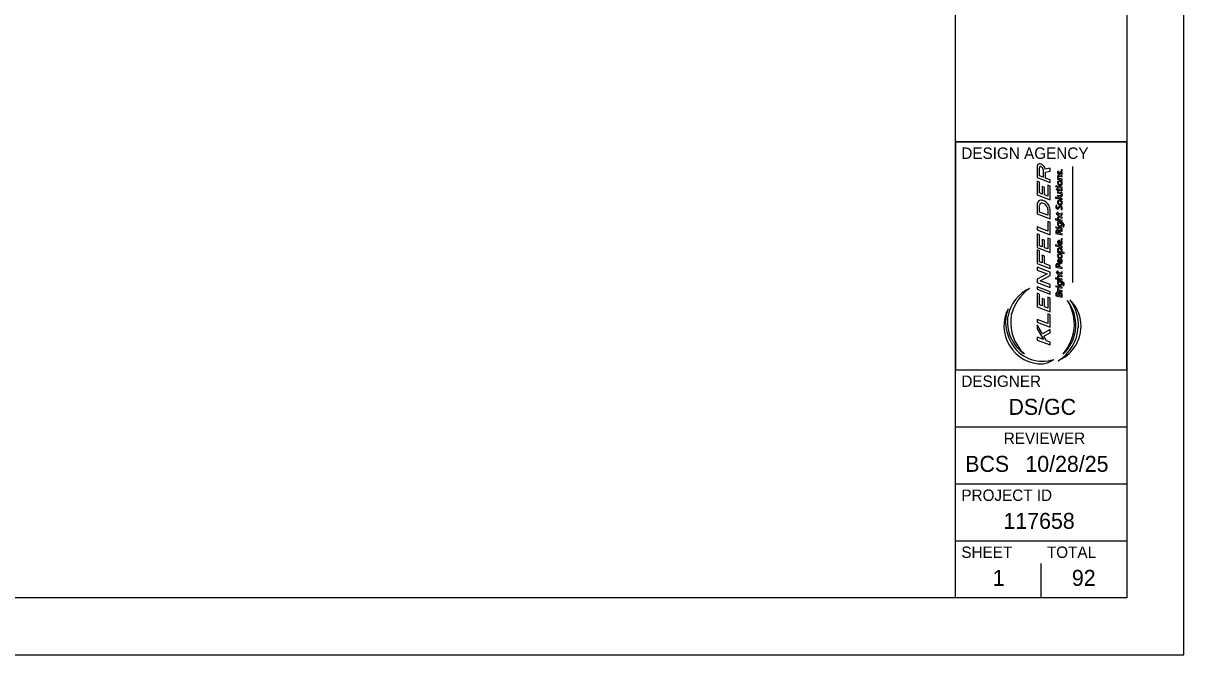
# Model space of a CAD drawing. Extents: x -107 to 120, y -81 to 213.
# Drawn here: x 27.71 to 37.89, y 1.57 to 7.11 of the extents above; entities that cross this region are included whole.
import ezdxf

# ---------------------------------------------------------------- set-up
doc = ezdxf.new("R2010")
doc.units = 0
for name, color, linetype in [('SC_Scratch1', 7, 'Continuous'), ('SH_Border', 7, 'Continuous'), ('SH_Cut_Line', 7, 'Continuous'), ('SH_Data', 7, 'Continuous'), ('SH_Text', 7, 'Continuous')]:
    doc.layers.add(name, color=color, linetype=linetype)

msp = doc.modelspace()

# ---------------------------------------------------------------- linework, layer by layer
at = {"layer": 'SC_Scratch1'}
msp.add_lwpolyline([(35.889, 4.068), (37.389, 4.068), (37.389, 6.068), (35.889, 6.068)], close=True, dxfattribs=at)
at = {"layer": 'SH_Border'}
for p, q in [((35.889, 2.068), (35.889, 23.068)), ((35.889, 6.068), (37.389, 6.068)), ((35.889, 4.068), (37.389, 4.068)), ((35.889, 3.568), (37.389, 3.568)), ((35.889, 3.068), (37.389, 3.068)), ((35.889, 2.568), (37.389, 2.568))]:
    msp.add_line(p, q, dxfattribs=at)
msp.add_lwpolyline([(5.389, 23.068), (37.389, 23.068), (37.389, 2.068), (5.389, 2.068)], close=True, dxfattribs=at)
at = {"layer": 'SH_Cut_Line'}
msp.add_lwpolyline([(3.889, 1.568), (37.889, 1.568), (37.889, 23.568), (3.889, 23.568)], close=True, dxfattribs=at)
at = {"layer": 'SH_Data'}
for p, q in [((36.639, 5.068), (36.639, 5.068)), ((36.639, 2.068), (36.639, 2.368)), ((36.264, 2.243), (36.264, 2.243))]:
    msp.add_line(p, q, dxfattribs=at)
at = {"layer": 'SH_Text'}
for p, q in [((36.624, 5.769), (36.624, 5.84)), ((36.79, 5.807), (36.784, 5.809)), ((36.816, 5.78), (36.822, 5.778)), ((36.814, 5.645), (36.789, 5.65)), ((36.823, 5.654), (36.817, 5.655)), ((36.777, 5.508), (36.769, 5.51)), ((36.813, 5.473), (36.821, 5.471)), ((36.823, 5.442), (36.817, 5.443)), ((36.825, 5.357), (36.782, 5.366)), ((36.831, 5.323), (36.838, 5.321)), ((36.791, 5.278), (36.791, 5.267)), ((36.799, 5.195), (36.799, 5.174)), ((36.822, 5.195), (36.815, 5.197)), ((36.799, 5.031), (36.799, 5.01)), ((36.822, 5.032), (36.815, 5.033)), ((36.794, 4.979), (36.794, 4.971)), ((36.801, 4.97), (36.801, 4.98)), ((36.823, 4.926), (36.817, 4.927)), ((36.825, 4.841), (36.782, 4.85)), ((36.831, 4.807), (36.838, 4.805)), ((36.792, 4.73), (36.792, 4.721)), ((36.817, 4.725), (36.817, 4.715))]:
    msp.add_line(p, q, dxfattribs=at)
for points in [[(36.604, 5.855), (36.604, 5.755), (36.718, 5.711), (36.718, 5.733), (36.676, 5.749), (36.676, 5.801), (36.718, 5.811), (36.718, 5.837), (36.675, 5.827)], [(36.655, 5.825), (36.655, 5.757), (36.624, 5.769)], [(36.815, 5.823), (36.815, 5.815), (36.823, 5.813), (36.823, 5.821), (36.815, 5.823)], [(36.913, 5.851), (36.913, 4.835)], [(36.604, 5.723), (36.604, 5.604), (36.718, 5.56), (36.718, 5.679), (36.698, 5.687), (36.698, 5.592), (36.669, 5.602), (36.669, 5.667), (36.648, 5.675), (36.648, 5.61), (36.624, 5.619), (36.624, 5.715), (36.604, 5.723)], [(36.788, 5.747), (36.782, 5.748), (36.782, 5.741), (36.823, 5.732), (36.823, 5.74), (36.8, 5.745)], [(36.795, 5.767), (36.823, 5.761), (36.823, 5.769), (36.798, 5.775)], [(36.766, 5.683), (36.766, 5.674), (36.774, 5.673), (36.774, 5.681), (36.766, 5.683)], [(36.789, 5.65), (36.789, 5.661), (36.782, 5.663), (36.782, 5.651), (36.77, 5.654), (36.773, 5.646), (36.782, 5.644), (36.782, 5.635), (36.789, 5.633), (36.789, 5.643), (36.813, 5.638)], [(36.782, 5.679), (36.782, 5.671), (36.823, 5.662), (36.823, 5.67), (36.782, 5.679)], [(36.817, 5.612), (36.823, 5.611), (36.823, 5.619), (36.782, 5.627), (36.782, 5.619), (36.806, 5.614)], [(36.81, 5.593), (36.782, 5.598), (36.782, 5.59), (36.807, 5.585)], [(36.604, 5.516), (36.604, 5.435), (36.718, 5.392), (36.718, 5.465)], [(36.697, 5.474), (36.697, 5.423), (36.625, 5.45), (36.625, 5.51)], [(36.764, 5.581), (36.764, 5.573), (36.823, 5.561), (36.823, 5.569), (36.764, 5.581)], [(36.782, 5.45), (36.782, 5.439), (36.77, 5.442), (36.773, 5.433), (36.782, 5.432), (36.782, 5.423), (36.789, 5.421), (36.789, 5.43), (36.813, 5.425)], [(36.814, 5.432), (36.789, 5.438), (36.789, 5.449), (36.782, 5.45)], [(36.797, 5.405), (36.823, 5.399), (36.823, 5.407), (36.797, 5.412)], [(36.604, 5.321), (36.604, 5.296), (36.718, 5.253), (36.718, 5.362), (36.698, 5.37), (36.698, 5.285), (36.604, 5.321)], [(36.787, 5.386), (36.763, 5.391), (36.763, 5.383), (36.823, 5.37), (36.823, 5.378), (36.802, 5.383)], [(36.766, 5.321), (36.766, 5.313), (36.774, 5.311), (36.774, 5.319), (36.766, 5.321)], [(36.782, 5.366), (36.782, 5.358), (36.789, 5.357)], [(36.782, 5.317), (36.782, 5.309), (36.823, 5.3), (36.823, 5.309), (36.782, 5.317)], [(36.803, 5.279), (36.823, 5.284), (36.823, 5.292), (36.8, 5.286)], [(36.648, 5.212), (36.648, 5.147), (36.624, 5.156), (36.624, 5.252), (36.604, 5.26), (36.604, 5.141), (36.718, 5.097), (36.718, 5.216), (36.698, 5.224), (36.698, 5.128), (36.669, 5.139), (36.669, 5.204), (36.648, 5.212)], [(36.768, 5.284), (36.768, 5.264), (36.823, 5.252), (36.823, 5.261), (36.798, 5.266), (36.798, 5.273)], [(36.791, 5.267), (36.774, 5.271), (36.774, 5.28)], [(36.809, 5.173), (36.805, 5.173), (36.805, 5.202), (36.802, 5.202)], [(36.815, 5.218), (36.815, 5.21), (36.823, 5.208), (36.823, 5.216), (36.815, 5.218)], [(36.648, 5.073), (36.648, 5.007), (36.625, 5.016), (36.625, 5.112), (36.604, 5.12), (36.604, 5.001), (36.718, 4.958), (36.718, 4.981), (36.669, 5), (36.669, 5.065), (36.648, 5.073)], [(36.764, 5.163), (36.764, 5.155), (36.823, 5.142), (36.823, 5.15), (36.764, 5.163)], [(36.788, 5.106), (36.782, 5.107), (36.782, 5.101), (36.84, 5.088), (36.84, 5.097), (36.818, 5.101)], [(36.768, 4.986), (36.768, 4.969), (36.823, 4.957), (36.823, 4.965), (36.801, 4.97)], [(36.809, 5.009), (36.805, 5.009), (36.805, 5.038), (36.802, 5.039)], [(36.604, 4.863), (36.604, 4.835), (36.718, 4.791), (36.718, 4.815), (36.63, 4.849), (36.718, 4.895), (36.718, 4.923), (36.604, 4.967), (36.604, 4.943), (36.691, 4.91), (36.604, 4.863)], [(36.782, 4.934), (36.782, 4.923), (36.77, 4.926), (36.773, 4.918), (36.782, 4.916), (36.782, 4.907), (36.789, 4.905), (36.789, 4.914), (36.813, 4.909)], [(36.794, 4.971), (36.774, 4.975), (36.774, 4.982)], [(36.814, 4.916), (36.789, 4.922), (36.789, 4.933), (36.782, 4.934)], [(36.797, 4.889), (36.823, 4.883), (36.823, 4.891), (36.797, 4.897)], [(36.604, 4.797), (36.604, 4.774), (36.718, 4.73), (36.718, 4.753), (36.604, 4.797)], [(36.787, 4.87), (36.763, 4.875), (36.763, 4.867), (36.823, 4.854), (36.823, 4.862), (36.802, 4.867)], [(36.766, 4.805), (36.766, 4.797), (36.774, 4.795), (36.774, 4.803), (36.766, 4.805)], [(36.782, 4.85), (36.782, 4.843), (36.789, 4.841)], [(36.782, 4.802), (36.782, 4.793), (36.823, 4.785), (36.823, 4.793), (36.782, 4.802)], [(36.789, 4.783), (36.782, 4.785), (36.782, 4.778)], [(36.604, 4.74), (36.604, 4.621), (36.718, 4.577), (36.718, 4.696), (36.698, 4.704), (36.698, 4.609), (36.669, 4.62), (36.669, 4.684), (36.648, 4.692), (36.648, 4.628), (36.624, 4.637), (36.624, 4.732), (36.604, 4.74)], [(36.768, 4.736), (36.768, 4.717), (36.823, 4.706), (36.823, 4.729)], [(36.792, 4.721), (36.774, 4.724), (36.774, 4.732)], [(36.788, 4.768), (36.782, 4.769), (36.782, 4.761), (36.823, 4.753), (36.823, 4.761), (36.8, 4.766)], [(36.817, 4.715), (36.798, 4.719), (36.798, 4.728)], [(36.604, 4.51), (36.604, 4.485), (36.718, 4.442), (36.718, 4.551), (36.698, 4.559), (36.698, 4.474), (36.604, 4.51)], [(36.604, 4.463), (36.604, 4.427), (36.658, 4.333), (36.604, 4.353), (36.604, 4.329), (36.718, 4.286), (36.718, 4.31), (36.684, 4.323), (36.661, 4.362), (36.718, 4.393), (36.718, 4.421), (36.649, 4.384), (36.604, 4.463)]]:
    msp.add_lwpolyline(points, dxfattribs=at)
for centre, radius, start, end in [((36.627, 5.853), 0.0235, 105.8602, 175.9527), ((36.623, 5.84), 0.0359, 63.9111, 93.4134), ((36.635, 5.84), 0.0116, 120.9282, 182.8587), ((36.633, 5.838), 0.0128, 71.295, 106.2465), ((36.628, 5.824), 0.0278, 3.188, 69.9483), ((36.617, 5.817), 0.059, 10.1322, 68.6534), ((36.805, 5.799), 0.0237, 155.8068, 177.518), ((36.798, 5.798), 0.0164, 172.9331, 212.9177), ((36.797, 5.799), 0.0105, 131.8722, 213.0859), ((36.813, 5.792), 0.0139, 114.5985, 155.8852), ((36.812, 5.792), 0.013, 67.7239, 111.621), ((36.808, 5.791), 0.0157, 25.7964, 57.936), ((36.796, 5.762), 0.0143, 136.2913, 182.0825), ((36.797, 5.76), 0.0157, 176.9051, 236.2062), ((36.802, 5.709), 0.0207, 134.8616, 186.3333), ((36.803, 5.708), 0.0218, 183.0085, 235.1138), ((36.793, 5.794), 0.0102, 205.2791, 253.4117), ((36.795, 5.759), 0.0157, 78.3727, 128.7252), ((36.798, 5.76), 0.0107, 164.3628, 217.5642), ((36.797, 5.709), 0.00982, 114.8029, 183.3912), ((36.799, 5.708), 0.0115, 178.7964, 222.8298), ((36.794, 5.76), 0.00751, 82.4034, 156.5016), ((36.8, 5.703), 0.0236, 80.4774, 121.3769), ((36.793, 5.796), 0.00472, 212.4264, 286.081), ((36.805, 5.764), 0.0192, 214.0093, 253.9548), ((36.806, 5.715), 0.0212, 222.6118, 267.8201), ((36.793, 5.793), 0.0096, 252.4577, 305.4949), ((36.8, 5.702), 0.0176, 73.9781, 113.6531), ((36.789, 5.802), 0.0117, 294.6007, 337.5251), ((36.788, 5.8), 0.018, 306.3564, 329.8219), ((36.826, 5.778), 0.0248, 133.1465, 150.3389), ((36.802, 5.705), 0.0217, 48.9189, 86.1506), ((36.8, 5.699), 0.0201, 30.777, 75.0314), ((36.807, 5.706), 0.0124, 261.6619, 324.7522), ((36.812, 5.793), 0.00487, 54.9774, 133.6656), ((36.81, 5.79), 0.0081, 0.828, 56.4407), ((36.803, 5.789), 0.0154, 324.4952, 5.8801), ((36.806, 5.707), 0.0181, 359.1065, 54.0048), ((36.806, 5.704), 0.0122, 333.802, 26.7946), ((36.805, 5.703), 0.0192, 318.3025, 9.3316), ((36.806, 5.79), 0.0183, 351.4651, 24.96), ((36.783, 5.792), 0.0413, 341.1844, 354.3531), ((36.804, 5.708), 0.0225, 234.7204, 275.0527), ((36.808, 5.702), 0.0164, 263.7465, 315.576), ((36.8, 5.596), 0.0192, 34.0093, 73.9548), ((36.811, 5.6), 0.00751, 262.4034, 336.5016), ((36.815, 5.646), 0.00899, 258.837, 329.2244), ((36.815, 5.649), 0.00406, 265.2766, 359.8271), ((36.808, 5.6), 0.0107, 344.3628, 37.5642), ((36.807, 5.649), 0.012, 359.8271, 33.4272), ((36.809, 5.599), 0.0157, 356.9051, 56.2062), ((36.81, 5.598), 0.0143, 316.2913, 2.0825), ((36.803, 5.649), 0.0207, 339.7319, 13.8876), ((36.652, 5.516), 0.0481, 135.8191, 179.4263), ((36.638, 5.52), 0.0358, 73.1779, 125.9306), ((36.645, 5.511), 0.0203, 112.5545, 180.292), ((36.644, 5.512), 0.0192, 70.7496, 111.8258), ((36.625, 5.467), 0.0911, 25.2799, 75.3517), ((36.636, 5.469), 0.0624, 24.8644, 76.4065), ((36.652, 5.475), 0.0458, 358.9317, 26.1463), ((36.633, 5.464), 0.0851, 0.5101, 28.8607), ((36.791, 5.499), 0.0246, 153.0923, 182.7278), ((36.802, 5.499), 0.0359, 182.7278, 201.3007), ((36.788, 5.499), 0.0144, 140.4782, 179.939), ((36.786, 5.498), 0.0124, 175.3728, 230.5265), ((36.802, 5.537), 0.0207, 134.8616, 186.3333), ((36.803, 5.536), 0.0218, 183.0085, 235.1138), ((36.777, 5.5), 0.0149, 299.565, 339.2556), ((36.797, 5.537), 0.00982, 114.8029, 183.3912), ((36.799, 5.536), 0.0115, 178.7964, 222.8298), ((36.8, 5.531), 0.0236, 80.4774, 121.3769), ((36.806, 5.543), 0.0212, 222.6118, 267.8201), ((36.804, 5.536), 0.0225, 234.7204, 275.0527), ((36.81, 5.487), 0.0202, 112.5492, 156.2929), ((36.8, 5.53), 0.0176, 73.9781, 113.6531), ((36.808, 5.486), 0.011, 90.8577, 158.2517), ((36.807, 5.488), 0.018, 58.4507, 105.0331), ((36.802, 5.533), 0.0217, 48.9189, 86.1506), ((36.8, 5.527), 0.0201, 30.777, 75.0314), ((36.807, 5.534), 0.0124, 261.6619, 324.7522), ((36.808, 5.53), 0.0164, 263.7465, 315.576), ((36.811, 5.6), 0.0157, 258.3727, 308.7252), ((36.807, 5.487), 0.0099, 7.9705, 84.8943), ((36.804, 5.487), 0.0199, 358.5943, 53.7031), ((36.806, 5.535), 0.0181, 359.1065, 54.0048), ((36.806, 5.532), 0.0122, 333.802, 26.7946), ((36.805, 5.531), 0.0192, 318.3025, 9.3316), ((36.783, 5.494), 0.0157, 207.7495, 253.8409), ((36.782, 5.496), 0.00909, 239.5135, 284.896), ((36.782, 5.494), 0.0158, 256.3758, 294.8902), ((36.798, 5.398), 0.017, 145.2436, 189.7855), ((36.794, 5.397), 0.0129, 185.2859, 235.9293), ((36.795, 5.399), 0.0141, 80.6828, 137.5266), ((36.796, 5.397), 0.00818, 136.5529, 210.7681), ((36.776, 5.5), 0.0238, 303.1236, 337.1341), ((36.795, 5.397), 0.00748, 78.1668, 139.4713), ((36.798, 5.485), 0.0192, 321.116, 10.1848), ((36.815, 5.434), 0.00899, 258.837, 329.2244), ((36.815, 5.436), 0.00406, 265.2766, 359.8271), ((36.807, 5.436), 0.012, 359.8271, 33.4272), ((36.792, 5.486), 0.0327, 332.8538, 1.7076), ((36.803, 5.437), 0.0207, 339.7319, 13.8876), ((36.782, 5.282), 0.0143, 114.3537, 174.3612), ((36.78, 5.28), 0.0163, 54.324, 105.2141), ((36.801, 5.344), 0.0195, 166.4234, 246.8498), ((36.793, 5.347), 0.0113, 111.6426, 168.888), ((36.798, 5.345), 0.0102, 156.145, 220.58), ((36.798, 5.344), 0.0105, 93.2154, 153.4686), ((36.806, 5.403), 0.0202, 210.678, 259.5619), ((36.806, 5.354), 0.0229, 224.9845, 280.2941), ((36.779, 5.278), 0.0187, 16.6516, 54.9416), ((36.805, 5.35), 0.0268, 243.1201, 290.541), ((36.799, 5.332), 0.0226, 65.4895, 96.081), ((36.805, 5.341), 0.0125, 4.6127, 71.2311), ((36.809, 5.34), 0.00874, 280.0175, 10.7991), ((36.808, 5.339), 0.0158, 297.2493, 349.812), ((36.808, 5.34), 0.0154, 347.3096, 45.7047), ((36.818, 5.333), 0.0181, 52.9431, 88.3704), ((36.822, 5.339), 0.0178, 23.5672, 81.0788), ((36.819, 5.335), 0.0158, 15.8406, 51.2557), ((36.816, 5.335), 0.0194, 322.3021, 11.6769), ((36.81, 5.335), 0.0312, 334.3125, 21.7018), ((36.784, 5.28), 0.00918, 126.0182, 180.1757), ((36.782, 5.277), 0.0111, 71.543, 108.457), ((36.794, 5.19), 0.0124, 112.1338, 170.4587), ((36.804, 5.188), 0.0226, 169.5031, 205.801), ((36.78, 5.277), 0.0113, 2.8048, 63.3705), ((36.796, 5.187), 0.00858, 117.3851, 158.6637), ((36.799, 5.187), 0.0119, 168.1247, 206.2564), ((36.798, 5.177), 0.0257, 81.9878, 109.8531), ((36.796, 5.183), 0.012, 75.5066, 109.4211), ((36.802, 5.28), 0.00573, 112.0732, 152.0788), ((36.804, 5.274), 0.00539, 102.6271, 185.8955), ((36.781, 5.182), 0.0374, 10.3368, 23.7103), ((36.777, 5.183), 0.047, 359.6882, 15.2269), ((36.797, 5.12), 0.016, 128.4644, 186.7325), ((36.799, 5.12), 0.0179, 186.9887, 232.7091), ((36.805, 5.188), 0.0231, 206.9109, 260.8013), ((36.799, 5.108), 0.0268, 74.1204, 115.3732), ((36.796, 5.118), 0.00899, 131.5529, 215.9721), ((36.801, 5.187), 0.0135, 203.2444, 260.0416), ((36.805, 5.122), 0.0182, 210.6491, 255.0946), ((36.799, 5.115), 0.0133, 76.6402, 131.7242), ((36.806, 5.12), 0.0167, 247.995, 291.3144), ((36.806, 5.186), 0.0209, 255.6438, 310.1539), ((36.8, 5.107), 0.0207, 43.01, 84.1033), ((36.803, 5.112), 0.0228, 23.9558, 80.548), ((36.807, 5.185), 0.0122, 278.9982, 314.1507), ((36.807, 5.115), 0.0114, 295.6576, 343.4617), ((36.808, 5.114), 0.0101, 346.7314, 48.3063), ((36.799, 5.186), 0.0187, 328.9592, 8.5627), ((36.806, 5.115), 0.0184, 309.5558, 17.4679), ((36.805, 5.182), 0.0192, 319.8498, 2.5151), ((36.783, 4.986), 0.0158, 126.8786, 177.6793), ((36.782, 4.982), 0.0183, 67.3357, 118.1453), ((36.784, 4.983), 0.00934, 123.5007, 184.662), ((36.783, 4.98), 0.0119, 57.2999, 110.5503), ((36.802, 5.069), 0.0207, 134.8616, 186.3333), ((36.803, 5.067), 0.0218, 183.0085, 235.1138), ((36.794, 5.026), 0.0124, 112.1338, 170.4587), ((36.804, 5.024), 0.0226, 169.5031, 205.801), ((36.805, 5.025), 0.0231, 206.9109, 260.8013), ((36.797, 5.069), 0.00982, 114.8029, 183.3912), ((36.799, 5.068), 0.0115, 178.7964, 222.8298), ((36.8, 5.063), 0.0236, 80.4774, 121.3769), ((36.796, 5.023), 0.00858, 117.3851, 158.6637), ((36.799, 5.024), 0.0119, 168.1247, 206.2564), ((36.801, 5.024), 0.0135, 203.2444, 260.0416), ((36.779, 4.979), 0.0145, 357.8598, 47.6882), ((36.806, 5.074), 0.0212, 222.6118, 267.8201), ((36.798, 5.013), 0.0257, 81.9878, 109.8531), ((36.782, 4.981), 0.0192, 355.6807, 65.6249), ((36.804, 5.068), 0.0225, 234.7204, 275.0527), ((36.796, 5.019), 0.012, 75.5066, 109.4211), ((36.8, 5.061), 0.0176, 73.9781, 113.6531), ((36.806, 5.022), 0.0209, 255.6438, 310.1539), ((36.802, 5.065), 0.0217, 48.9189, 86.1506), ((36.8, 5.059), 0.0201, 30.777, 75.0314), ((36.807, 5.066), 0.0124, 261.6619, 324.7522), ((36.808, 5.062), 0.0164, 263.7465, 315.576), ((36.807, 5.021), 0.0122, 278.9982, 314.1507), ((36.781, 5.018), 0.0374, 10.3368, 23.7103), ((36.799, 5.022), 0.0187, 328.9592, 8.5627), ((36.806, 5.066), 0.0181, 359.1065, 54.0048), ((36.806, 5.064), 0.0122, 333.802, 26.7946), ((36.805, 5.063), 0.0192, 318.3025, 9.3316), ((36.805, 5.018), 0.0192, 319.8498, 2.5151), ((36.777, 5.019), 0.047, 359.6882, 15.2269), ((36.798, 4.882), 0.017, 145.2436, 189.7855), ((36.795, 4.883), 0.0141, 80.6828, 137.5266), ((36.796, 4.881), 0.00818, 136.5529, 210.7681), ((36.795, 4.881), 0.00748, 78.1668, 139.4713), ((36.815, 4.918), 0.00899, 258.837, 329.2244), ((36.815, 4.921), 0.00406, 265.2766, 359.8271), ((36.807, 4.921), 0.012, 359.8271, 33.4272), ((36.803, 4.921), 0.0207, 339.7319, 13.8876), ((36.801, 4.828), 0.0195, 166.4234, 246.8498), ((36.794, 4.881), 0.0129, 185.2859, 235.9293), ((36.793, 4.831), 0.0113, 111.6426, 168.888), ((36.798, 4.829), 0.0102, 156.145, 220.58), ((36.798, 4.828), 0.0105, 93.2154, 153.4686), ((36.798, 4.779), 0.00995, 158.8231, 202.4085), ((36.806, 4.887), 0.0202, 210.678, 259.5619), ((36.806, 4.838), 0.0229, 224.9845, 280.2941), ((36.805, 4.834), 0.0268, 243.1201, 290.541), ((36.799, 4.816), 0.0226, 65.4895, 96.081), ((36.805, 4.825), 0.0125, 4.6127, 71.2311), ((36.809, 4.824), 0.00874, 280.0175, 10.7991), ((36.808, 4.823), 0.0158, 297.2493, 349.812), ((36.808, 4.824), 0.0154, 347.3096, 45.7047), ((36.818, 4.817), 0.0181, 52.9431, 88.3704), ((36.822, 4.823), 0.0178, 23.5672, 81.0788), ((36.819, 4.819), 0.0158, 15.8406, 51.2557), ((36.816, 4.819), 0.0194, 322.3021, 11.6769), ((36.81, 4.819), 0.0312, 334.3125, 21.7018), ((36.681, 4.474), 0.34, 115.1143, 168.3777), ((36.76, 4.457), 0.394, 124.4536, 166.9641), ((36.782, 4.735), 0.0148, 118.8217, 177.6001), ((36.782, 4.733), 0.00845, 104.5669, 183.2204), ((36.78, 4.732), 0.0165, 47.423, 108.0377), ((36.782, 4.733), 0.0084, 40.2808, 100.5581), ((36.796, 4.78), 0.0136, 188.2387, 237.9511), ((36.776, 4.728), 0.0155, 3.7446, 38.6277), ((36.806, 4.784), 0.0194, 205.713, 250.7037), ((36.775, 4.734), 0.0195, 8.6642, 31.5112), ((36.806, 4.733), 0.0129, 99.5096, 160.7154), ((36.806, 4.73), 0.00818, 113.2405, 191.7775), ((36.806, 4.73), 0.00788, 58.3862, 113.2405), ((36.807, 4.733), 0.0131, 56.795, 103.6323), ((36.803, 4.725), 0.0135, 1.8674, 60.8259), ((36.803, 4.727), 0.0207, 4.8421, 55.7541), ((36.66, 4.45), 0.328, 325.1289, 45.2058), ((36.589, 4.459), 0.376, 357.0055, 36.4292), ((36.66, 4.45), 0.328, 325.1289, 45.2058), ((36.589, 4.459), 0.376, 357.0055, 36.4292), ((36.645, 4.453), 0.333, 153.0899, 211.3353), ((36.69, 4.481), 0.363, 160.2384, 179.8908), ((36.488, 4.452), 0.443, 1.2686, 30.3182), ((36.595, 4.462), 0.347, 356.3155, 37.8631), ((36.721, 4.496), 0.394, 182.1375, 213.7556), ((36.68, 4.488), 0.337, 170.6744, 236.0558), ((36.744, 4.483), 0.373, 170.3407, 217.7725), ((36.594, 4.463), 0.37, 301.6203, 356.4398), ((36.594, 4.463), 0.37, 301.6203, 356.4398), ((36.515, 4.477), 0.415, 319.4476, 357.9721), ((36.595, 4.462), 0.348, 312.6314, 356.3155), ((36.644, 4.45), 0.33, 210.9374, 272.3516), ((36.65, 4.456), 0.313, 214.7279, 288.5434), ((36.693, 4.443), 0.309, 217.7725, 229.547), ((36.657, 4.452), 0.331, 293.3176, 325.0704), ((36.657, 4.452), 0.331, 293.3176, 325.0704), ((36.608, 4.365), 0.25, 281.4129, 304.5262)]:
    msp.add_arc(centre, radius, start, end, dxfattribs=at)

# ---------------------------------------------------------------- texts
at = {"layer": 'SH_Data'}
for s, height, p in [('DESIGN AGENCY', 0.1, (35.939, 5.918)), ('DESIGNER', 0.1, (35.939, 3.918)), ('DS/GC', 0.14, (36.352, 3.673)), ('REVIEWER', 0.1, (36.311, 3.418)), ('BCS', 0.14, (35.973, 3.173)), ('10/28/25', 0.14, (36.5, 3.173)), ('PROJECT ID', 0.1, (35.939, 2.918)), ('117658', 0.14, (36.308, 2.673)), ('SHEET', 0.1, (35.939, 2.418)), ('TOTAL', 0.1, (36.689, 2.418)), ('1', 0.14, (36.214, 2.173)), ('92', 0.14, (36.908, 2.173))]:
    msp.add_text(s, height=height, dxfattribs=at).set_placement(p)

doc.saveas('drawing.dxf')
